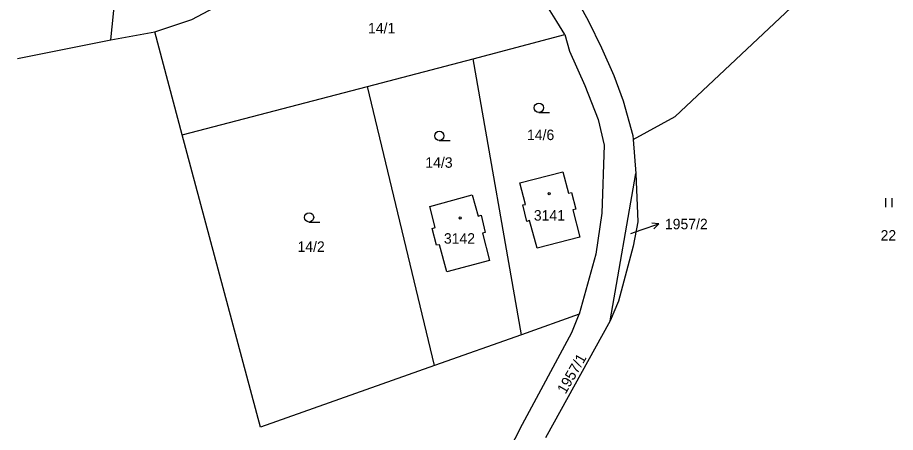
# Model space of a CAD drawing. Extents: x -866656 to -858817, y -1041816 to -1038653.
# Drawn here: x -865754.8 to -865612.1, y -1040103.2 to -1040035.8 of the extents above; entities that cross this region are included whole.
import ezdxf

# ---------------------------------------------------------------- set-up
doc = ezdxf.new("R2010")
doc.units = 0
for name, color, linetype in [('Hranice parcel', 7, 'Continuous'), ('Parcelní čísla', 7, 'Continuous'), ('Pop  PČ popisy', 7, 'Continuous'), ('Značky budov', 7, 'Continuous'), ('Značky kultur', 7, 'Continuous')]:
    doc.layers.add(name, color=color, linetype=linetype)

msp = doc.modelspace()

# ---------------------------------------------------------------- linework, layer by layer
at = {"layer": 'Hranice parcel'}
for p, q in [((-865739.62, -1040039.41), (-865733.59, -1039980.1)), ((-865647.91, -1040051.87), (-865616.49, -1040022.34)), ((-865665.38, -1040030.22), (-865662.01, -1040036.36)), ((-865667.12, -1040036.46), (-865669.66, -1040032.4)), ((-865726.48, -1040036.09), (-865721.03, -1040033.22)), ((-865732.48, -1040038.13), (-865726.48, -1040036.09)), ((-865665.84, -1040038.55), (-865667.12, -1040036.46)), ((-865662.01, -1040036.36), (-865659.87, -1040040.74)), ((-865739.62, -1040039.41), (-865732.48, -1040038.13)), ((-865728.04, -1040054.86), (-865732.48, -1040038.13)), ((-865754.8, -1040042.47), (-865739.62, -1040039.41)), ((-865680.76, -1040042.49), (-865665.84, -1040038.55)), ((-865665.84, -1040038.55), (-865665.06, -1040041.27)), ((-865665.06, -1040041.27), (-865662.56, -1040046.87)), ((-865659.87, -1040040.74), (-865657.89, -1040045.24)), ((-865697.89, -1040047.01), (-865680.76, -1040042.49)), ((-865672.9, -1040087.36), (-865680.76, -1040042.49)), ((-865657.89, -1040045.24), (-865656.37, -1040049.32)), ((-865728.04, -1040054.86), (-865697.89, -1040047.01)), ((-865687.03, -1040092.36), (-865697.89, -1040047.01)), ((-865662.56, -1040046.87), (-865660.44, -1040052.4)), ((-865656.37, -1040049.32), (-865654.78, -1040054.99)), ((-865660.44, -1040052.4), (-865659.43, -1040056.56)), ((-865654.73, -1040055.63), (-865647.91, -1040051.87)), ((-865715.29, -1040102.37), (-865728.04, -1040054.86)), ((-865654.78, -1040054.99), (-865654.73, -1040055.63)), ((-865659.43, -1040056.56), (-865659.81, -1040067.61)), ((-865654.73, -1040055.63), (-865654.27, -1040061.14)), ((-865673.17, -1040062.66), (-865666.14, -1040060.86)), ((-865666.14, -1040060.86), (-865665.25, -1040064.36)), ((-865658.49, -1040085.13), (-865654.27, -1040061.14)), ((-865654.27, -1040061.14), (-865653.94, -1040069.01)), ((-865672.25, -1040066.18), (-865673.17, -1040062.66)), ((-865687.8, -1040066.51), (-865680.88, -1040064.63)), ((-865680.88, -1040064.63), (-865679.91, -1040068.09)), ((-865665.25, -1040064.36), (-865664.76, -1040064.24)), ((-865664.76, -1040064.24), (-865664.07, -1040066.93)), ((-865686.93, -1040069.95), (-865687.8, -1040066.51)), ((-865672.67, -1040066.27), (-865672.25, -1040066.18)), ((-865672.01, -1040068.94), (-865672.67, -1040066.27)), ((-865664.07, -1040066.93), (-865664.54, -1040067.07)), ((-865679.91, -1040068.09), (-865679.46, -1040067.94)), ((-865679.46, -1040067.94), (-865678.77, -1040070.73)), ((-865664.54, -1040067.07), (-865663.39, -1040071.53)), ((-865659.81, -1040067.61), (-865660.78, -1040074.27)), ((-865671.59, -1040068.81), (-865672.01, -1040068.94)), ((-865670.35, -1040073.31), (-865671.59, -1040068.81)), ((-865653.94, -1040069.01), (-865654.72, -1040072.95)), ((-865687.4, -1040070.1), (-865686.93, -1040069.95)), ((-865686.69, -1040072.82), (-865687.4, -1040070.1)), ((-865678.77, -1040070.73), (-865679.21, -1040070.85)), ((-865679.21, -1040070.85), (-865678.06, -1040075.31)), ((-865663.39, -1040071.53), (-865670.35, -1040073.31)), ((-865686.22, -1040072.75), (-865686.69, -1040072.82)), ((-865685.04, -1040077.14), (-865686.22, -1040072.75)), ((-865654.72, -1040072.95), (-865657.11, -1040081.91)), ((-865678.06, -1040075.31), (-865685.04, -1040077.14)), ((-865660.78, -1040074.27), (-865663.48, -1040084.02)), ((-865657.11, -1040081.91), (-865658.49, -1040085.13)), ((-865663.48, -1040084.02), (-865672.9, -1040087.36)), ((-865664.7, -1040087.02), (-865663.48, -1040084.02)), ((-865658.49, -1040085.13), (-865669, -1040104.13)), ((-865672.9, -1040087.36), (-865687.03, -1040092.36)), ((-865672.73, -1040101.88), (-865664.7, -1040087.02)), ((-865687.03, -1040092.36), (-865715.29, -1040102.37)), ((-865687.66, -1040131.53), (-865672.73, -1040101.88))]:
    msp.add_line(p, q, dxfattribs=at)
at = {"layer": 'Pop  PČ popisy'}
for p, q in [((-865653.4, -1040070.32), (-865650.56, -1040069.34)), ((-865650.56, -1040069.34), (-865651.67, -1040069.2)), ((-865650.56, -1040069.34), (-865651.35, -1040070.14)), ((-865655.12, -1040070.9), (-865653.4, -1040070.32))]:
    msp.add_line(p, q, dxfattribs=at)
at = {"layer": 'Značky budov'}
for centre in [(-865668.38, -1040064.43), (-865682.85, -1040068.38)]:
    msp.add_circle(centre, 0.175, dxfattribs=at)
at = {"layer": 'Značky kultur'}
for p, q in [((-865670.05, -1040051.22), (-865668.3, -1040051.22)), ((-865686.24, -1040055.79), (-865684.49, -1040055.79)), ((-865613.63, -1040066.65), (-865613.63, -1040065.15)), ((-865612.63, -1040066.65), (-865612.63, -1040065.15)), ((-865707.41, -1040069.04), (-865705.66, -1040069.04))]:
    msp.add_line(p, q, dxfattribs=at)
for centre in [(-865670.05, -1040050.47), (-865686.24, -1040055.04), (-865707.41, -1040068.29)]:
    msp.add_circle(centre, 0.75, dxfattribs=at)

# ---------------------------------------------------------------- texts
at = {"layer": 'Parcelní čísla'}
for s, p in [('14/1', (-865697.82, -1040038.37)), ('14/6', (-865671.98, -1040055.72)), ('14/3', (-865688.5, -1040060.22)), ('3141', (-865670.87, -1040068.81)), ('1957/2', (-865649.56, -1040070.22)), ('3142', (-865685.49, -1040072.56)), ('22', (-865614.5, -1040072.06)), ('14/2', (-865709.29, -1040073.89))]:
    msp.add_text(s, height=1.7, dxfattribs=at).set_placement(p)
msp.add_text('1957/1', height=1.7, rotation=60, dxfattribs=at).set_placement((-865665.72, -1040097.11))

doc.saveas('drawing.dxf')
